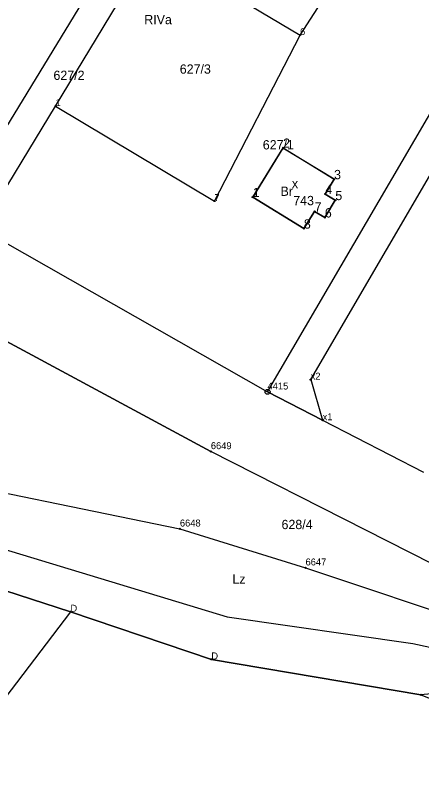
# Model space of a CAD drawing. Extents: x 7465393 to 7466459, y 5491258 to 5492404.
# Drawn here: x 7466056.8 to 7466122.4, y 5491451.3 to 5491575.9 of the extents above; entities that cross this region are included whole.
import ezdxf

# ---------------------------------------------------------------- set-up
doc = ezdxf.new("R2010")
doc.units = 0
for name, color, linetype in [('202-punkt graniczny', 7, 'Continuous'), ('202-punkt graniczny-Atr103', 7, 'Continuous'), ('203-punkt graniczny', 7, 'Continuous'), ('203-punkt graniczny-Atr103', 7, 'Continuous'), ('209-oznaczenie konturu klasyfikacyjnego', 7, 'Continuous'), ('210-oznaczenie konturu użytku gruntowego', 7, 'Continuous'), ('211-numer działki ewidencyjnej', 7, 'Continuous'), ('217-kontur klasyfikacyjny', 7, 'Continuous'), ('218-kontur użytku gruntowego', 7, 'Continuous'), ('219-działka ewidencyjna', 7, 'Continuous'), ('312-budynek ewidencyjny', 7, 'Continuous'), ('312-oznaczenie budynku ewidencyjnego', 7, 'Continuous'), ('312-oznaczenie budynku ewidencyjnego-Atr117', 7, 'Continuous'), ('Punkt budynku', 7, 'Continuous'), ('Punkt budynku-Atr104', 7, 'Continuous')]:
    doc.layers.add(name, color=color, linetype=linetype)

# ---------------------------------------------------------------- blocks, each defined once
blk = doc.blocks.new('203')
blk.add_circle((0, 0), 0.09)
blk = doc.blocks.new('202')
blk.add_circle((0, 0), 0.4)
blk = doc.blocks.new('PUNKTBUD')
blk.add_circle((0, 0), 0.09)

msp = doc.modelspace()

# ---------------------------------------------------------------- linework, layer by layer
at = {"layer": '217-kontur klasyfikacyjny'}
for points in [[(7466051.21, 5491541.46), (7466097.56, 5491515.12)], [(7466097.56, 5491515.12), (7466106.46, 5491510.53)], [(7466106.46, 5491510.53), (7466122.75, 5491502.13)], [(7466065.72, 5491479.6), (7466048.73, 5491485.09)], [(7466088.48, 5491471.89), (7466065.72, 5491479.6)], [(7466122.34, 5491466.17), (7466088.48, 5491471.89)], [(7466135.74, 5491467.47), (7466122.34, 5491466.17)]]:
    msp.add_lwpolyline(points, dxfattribs=at)
at = {"layer": '218-kontur użytku gruntowego'}
for points in [[(7466100.05, 5491554.5), (7466095.16, 5491546.58)], [(7466108.31, 5491549.48), (7466100.05, 5491554.5)], [(7466106.88, 5491547.08), (7466108.31, 5491549.48)], [(7466095.16, 5491546.58), (7466103.43, 5491541.5)], [(7466108.51, 5491546.1), (7466106.88, 5491547.08)], [(7466106.82, 5491543.3), (7466108.51, 5491546.1)], [(7466103.43, 5491541.5), (7466105.17, 5491544.26)], [(7466105.17, 5491544.26), (7466106.82, 5491543.3)], [(7466051.21, 5491541.46), (7466097.56, 5491515.12)], [(7466088.4, 5491505.48), (7466052.56, 5491524.79)], [(7466097.56, 5491515.12), (7466106.46, 5491510.53)], [(7466106.46, 5491510.53), (7466122.75, 5491502.13)], [(7466138.5, 5491480.05), (7466088.4, 5491505.48)], [(7466038.23, 5491502.27), (7466083.4, 5491492.98)], [(7466083.4, 5491492.98), (7466103.7, 5491486.69)], [(7466051.37, 5491490.77), (7466091.01, 5491478.79)], [(7466103.7, 5491486.69), (7466132.1, 5491477.18)], [(7466065.72, 5491479.6), (7466048.73, 5491485.09)], [(7466088.48, 5491471.89), (7466065.72, 5491479.6)], [(7466091.01, 5491478.79), (7466121.01, 5491474.47)], [(7466121.01, 5491474.47), (7466137.53, 5491470.91)], [(7466122.34, 5491466.17), (7466088.48, 5491471.89)], [(7466135.74, 5491467.47), (7466122.34, 5491466.17)]]:
    msp.add_lwpolyline(points, dxfattribs=at)
at = {"layer": '219-działka ewidencyjna'}
for points in [[(7466102.82, 5491572.78), (7466118.45, 5491597.01)], [(7466063.32, 5491561.29), (7466078.85, 5491587.02)], [(7466078.85, 5491587.02), (7466102.82, 5491572.78)], [(7466046.97, 5491544.21), (7466071.15, 5491583.85)], [(7466097.56, 5491515.12), (7466137.33, 5491583.27)], [(7466088.98, 5491545.95), (7466102.82, 5491572.78)], [(7466051.21, 5491541.46), (7466063.32, 5491561.29)], [(7466063.32, 5491561.29), (7466088.98, 5491545.95)], [(7466104.53, 5491517.09), (7466128.99, 5491559.04)], [(7466051.21, 5491541.46), (7466097.56, 5491515.12)], [(7466052.56, 5491524.79), (7466088.4, 5491505.48)], [(7466104.53, 5491517.09), (7466106.46, 5491510.53)], [(7466106.46, 5491510.53), (7466097.56, 5491515.12)], [(7466106.46, 5491510.53), (7466122.75, 5491502.13)], [(7466138.5, 5491480.05), (7466088.4, 5491505.48)], [(7466038.23, 5491502.27), (7466083.4, 5491492.98)], [(7466083.4, 5491492.98), (7466103.7, 5491486.69)], [(7466103.7, 5491486.69), (7466132.1, 5491477.18)], [(7466048.73, 5491485.09), (7466065.72, 5491479.6)], [(7466065.72, 5491479.6), (7466023.22, 5491423.79)], [(7466065.72, 5491479.6), (7466088.48, 5491471.89)], [(7466088.48, 5491471.89), (7466122.34, 5491466.17)], [(7466122.34, 5491466.17), (7466147.45, 5491456.12)]]:
    msp.add_lwpolyline(points, dxfattribs=at)
at = {"layer": '312-budynek ewidencyjny'}
for points in [[(7466095.16, 5491546.58), (7466100.08, 5491554.55)], [(7466100.08, 5491554.55), (7466108.31, 5491549.48)], [(7466108.31, 5491549.48), (7466106.88, 5491547.08)], [(7466103.43, 5491541.5), (7466095.16, 5491546.58)], [(7466106.88, 5491547.08), (7466108.51, 5491546.1)], [(7466108.51, 5491546.1), (7466106.82, 5491543.3)], [(7466105.17, 5491544.26), (7466103.43, 5491541.5)], [(7466106.82, 5491543.3), (7466105.17, 5491544.26)]]:
    msp.add_lwpolyline(points, dxfattribs=at)

# ---------------------------------------------------------------- block references
at = {"layer": '202-punkt graniczny'}
msp.add_blockref('202', (7466097.56, 5491515.12), dxfattribs=at)
at = {"layer": '203-punkt graniczny'}
for p in [(7466102.82, 5491572.78), (7466063.32, 5491561.29), (7466088.98, 5491545.95), (7466104.53, 5491517.09), (7466106.46, 5491510.53), (7466088.4, 5491505.48), (7466083.4, 5491492.98), (7466103.7, 5491486.69), (7466065.72, 5491479.6), (7466088.48, 5491471.89), (7466122.34, 5491466.17)]:
    msp.add_blockref('203', p, dxfattribs=at)
at = {"layer": 'Punkt budynku'}
for p in [(7466100.08, 5491554.55), (7466108.31, 5491549.48), (7466095.16, 5491546.58), (7466106.88, 5491547.08), (7466108.51, 5491546.1), (7466105.17, 5491544.26), (7466106.82, 5491543.3), (7466103.43, 5491541.5)]:
    msp.add_blockref('PUNKTBUD', p, dxfattribs=at)

# ---------------------------------------------------------------- texts
at = {"layer": '202-punkt graniczny-Atr103'}
msp.add_text('4415', height=1.125, dxfattribs=at).set_placement((7466097.56, 5491515.5))
at = {"layer": '203-punkt graniczny-Atr103'}
for s, height, p in [('6', 1.12, (7466102.82, 5491572.78)), ('1', 1.12, (7466063.32, 5491561.29)), ('7', 1.12, (7466088.98, 5491545.95)), ('x2', 1.125, (7466104.53, 5491517.09)), ('x1', 1.125, (7466106.46, 5491510.53)), ('6649', 1.125, (7466088.4, 5491505.86)), ('6648', 1.125, (7466083.4, 5491493.36)), ('6647', 1.125, (7466103.7, 5491487.07)), ('D', 1.12, (7466065.72, 5491479.6)), ('D', 1.12, (7466088.48, 5491471.89))]:
    msp.add_text(s, height=height, dxfattribs=at).set_placement(p)
at = {"layer": '209-oznaczenie konturu klasyfikacyjnego'}
msp.add_text('RIVa', height=1.5, dxfattribs=at).set_placement((7466077.64, 5491574.52))
at = {"layer": '210-oznaczenie konturu użytku gruntowego'}
for s, p in [('Br', (7466099.66, 5491546.79)), ('Lz', (7466091.88, 5491484.13))]:
    msp.add_text(s, height=1.5, dxfattribs=at).set_placement(p)
at = {"layer": '211-numer działki ewidencyjnej'}
for s, p in [('627/3', (7466083.38, 5491566.53)), ('627/2', (7466062.97, 5491565.52)), ('627/1', (7466096.79, 5491554.29)), ('628/4', (7466099.82, 5491492.94))]:
    msp.add_text(s, height=1.5, dxfattribs=at).set_placement(p)
at = {"layer": '312-oznaczenie budynku ewidencyjnego'}
msp.add_text('743', height=1.5, dxfattribs=at).set_placement((7466101.71, 5491545.28))
at = {"layer": '312-oznaczenie budynku ewidencyjnego-Atr117'}
msp.add_text('x', height=1.5, dxfattribs=at).set_placement((7466101.49, 5491548.03))
at = {"layer": 'Punkt budynku-Atr104'}
for s, p in [('2', (7466100.08, 5491554.55)), ('3', (7466108.31, 5491549.48)), ('1', (7466095.16, 5491546.58)), ('4', (7466106.88, 5491547.08)), ('5', (7466108.51, 5491546.1)), ('7', (7466105.17, 5491544.26)), ('6', (7466106.82, 5491543.3)), ('8', (7466103.43, 5491541.5))]:
    msp.add_text(s, height=1.5, dxfattribs=at).set_placement(p)

doc.saveas('drawing.dxf')
